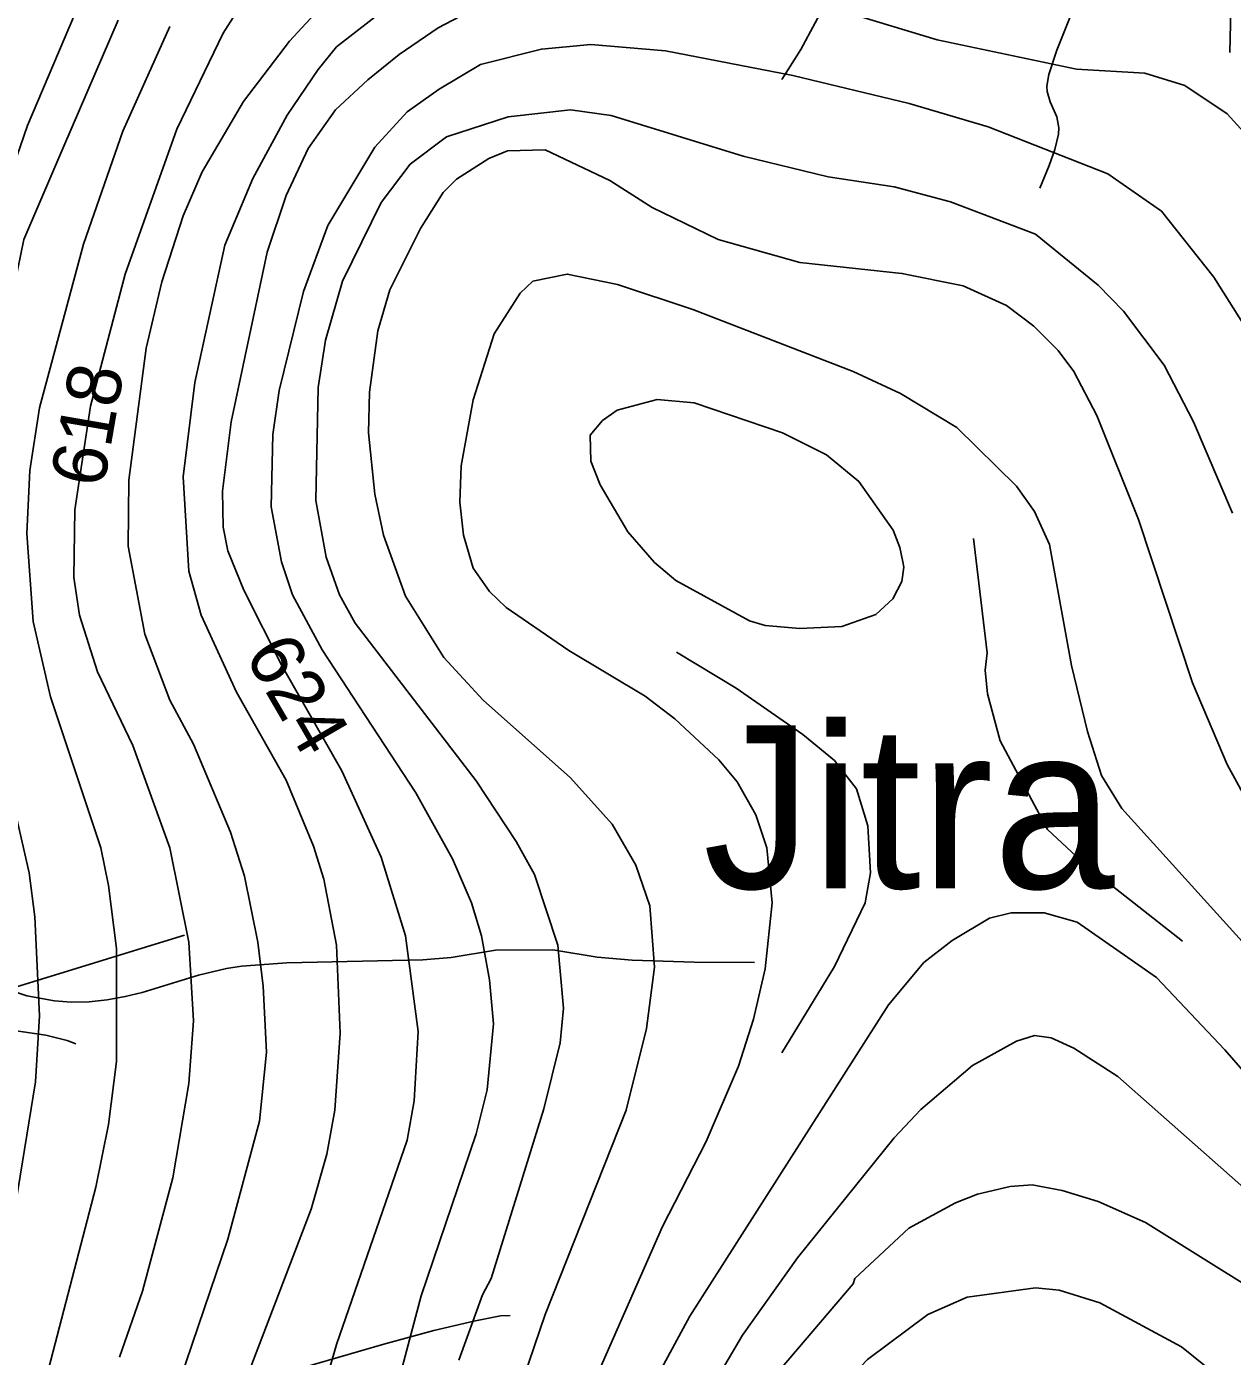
# Model space of a CAD drawing. Extents: x -709584 to -702006, y -1161789 to -1157496.
# Drawn here: x -708273.5 to -708051.5, y -1159639.5 to -1159394.7 of the extents above; entities that cross this region are included whole.
import ezdxf

# ---------------------------------------------------------------- set-up
doc = ezdxf.new("R2010")
doc.units = 0
for name, color, linetype in [('105_místní názvy', 7, 'Continuous'), ('120_vrstevnice hlavní', 7, 'Continuous'), ('121_vrstevnice hlavní_popis', 7, 'Continuous'), ('122_vrstevnice základní', 7, 'Continuous'), ('124_vrstevnice doplňková', 7, 'Continuous'), ('411_akumulovaný odtok', 7, 'Continuous')]:
    doc.layers.add(name, color=color, linetype=linetype)

msp = doc.modelspace()

# ---------------------------------------------------------------- linework, layer by layer
at = {"layer": '120_vrstevnice hlavní'}
for points in [[(-708006.36, -1159424.2), (-708009.48, -1159411.26), (-708013.71, -1159401.03), (-708020.47, -1159391.18), (-708024.76, -1159387.18), (-708031.9, -1159381.61), (-708039.33, -1159378.18), (-708046.76, -1159376.18), (-708054.19, -1159375.75), (-708072.76, -1159376.03), (-708087.62, -1159375.03), (-708105.04, -1159371.89), (-708125.62, -1159365.46), (-708142.76, -1159362.32), (-708156.48, -1159361.46), (-708170.19, -1159361.75), (-708187.33, -1159366.03), (-708197.62, -1159371.75), (-708206.77, -1159378.39), (-708217.52, -1159389.17), (-708225.11, -1159397.44)], [(-708225.12, -1159397.44), (-708233.59, -1159408.55), (-708241.24, -1159421.51), (-708244.71, -1159429.61), (-708248.62, -1159441.76), (-708251.51, -1159453.91), (-708254.69, -1159478.21), (-708254.83, -1159490.36), (-708251.8, -1159506.56), (-708247.17, -1159518.71), (-708242.83, -1159526.81), (-708236.03, -1159543.01), (-708233.43, -1159551.11), (-708230.97, -1159563.26), (-708229.96, -1159571.36), (-708229.38, -1159583.51), (-708230.68, -1159596.24), (-708236.46, -1159617.94), (-708246.3, -1159646.87)], [(-708044.23, -1159545.62), (-708052.48, -1159530.57), (-708058.84, -1159515.53), (-708068.82, -1159485.45), (-708076.49, -1159466.35), (-708080.68, -1159458.25), (-708083.58, -1159454.35), (-708088.06, -1159449.86), (-708093.12, -1159446.1), (-708101.08, -1159442.49), (-708112.36, -1159440.17), (-708131.16, -1159438.15), (-708146.21, -1159433.95), (-708158.36, -1159428.02), (-708166.17, -1159423.1), (-708178.03, -1159417.46), (-708184.97, -1159417.61), (-708188.44, -1159419.05), (-708194.37, -1159422.81), (-708196.83, -1159425.27), (-708201.03, -1159431.93), (-708206.67, -1159443.21), (-708208.84, -1159450.73), (-708210.43, -1159462.01), (-708210.57, -1159469.53), (-708209.42, -1159480.82), (-708207.83, -1159488.34), (-708203.78, -1159499.62), (-708196.69, -1159510.9), (-708189.46, -1159518.71), (-708173.4, -1159533.03), (-708165.73, -1159541.57), (-708161.39, -1159549.09), (-708158.79, -1159556.61), (-708157.92, -1159567.89), (-708159.37, -1159579.18), (-708163.13, -1159594.22), (-708178.03, -1159631.82)], [(-708183.23, -1159919.09), (-708173.43, -1159906.12), (-708162.84, -1159889.73), (-708160.09, -1159880.61), (-708157.2, -1159867.6), (-708155.9, -1159854.58), (-708155.9, -1159841.56), (-708158.36, -1159801.2), (-708156.91, -1159759.69), (-708152.86, -1159729.61), (-708146.93, -1159695.76), (-708139.26, -1159673.19), (-708133.97, -1159661.41), (-708125.81, -1159647.59), (-708118.72, -1159640.07), (-708107.59, -1159631.82), (-708100.35, -1159628.64), (-708087.77, -1159626.91), (-708083.43, -1159627.34), (-708075.91, -1159629.66), (-708060.87, -1159637.76), (-708033.09, -1159660.18)], [(-708178.03, -1159631.82), (-708187, -1159658.15), (-708192.93, -1159684.48), (-708196.98, -1159707.04), (-708201.9, -1159740.89), (-708203.49, -1159759.69), (-708204.35, -1159783.99), (-708202.18, -1159825.65), (-708204.06, -1159841.56), (-708207.39, -1159853.71), (-708214.33, -1159872.8), (-708235.16, -1159914.17), (-708252.09, -1159951.78), (-708262.21, -1159970.58), (-708281.88, -1159998.93), (-708292.44, -1160017.74), (-708313.42, -1160064.02), (-708336.41, -1160105.97)]]:
    msp.add_lwpolyline(points, dxfattribs=at)
msp.add_open_spline([(-708225.11, -1159397.44), (-708225.12, -1159397.44)], degree=1, dxfattribs=at)
at = {"layer": '122_vrstevnice základní'}
for points in [[(-708237.32, -1159395.95), (-708230.54, -1159385.25), (-708221.75, -1159375.45), (-708212.63, -1159367.61), (-708198.19, -1159358.18), (-708191.33, -1159354.89), (-708187.19, -1159353.75), (-708187.05, -1159353.32), (-708175.05, -1159350.6), (-708165.05, -1159349.46), (-708157.05, -1159349.46), (-708145.05, -1159350.6), (-708132.19, -1159353.17), (-708110.76, -1159358.75), (-708081.33, -1159363.18), (-708041.33, -1159363.75), (-708030.18, -1159365.89), (-708023.33, -1159368.75), (-708017.61, -1159373.03), (-708012.33, -1159378.75), (-708004.75, -1159390.46), (-708000.69, -1159398.78), (-707996.45, -1159413.48), (-707994.48, -1159425.66)], [(-708021.96, -1159422.29), (-708025.43, -1159412.46), (-708028.69, -1159406.91), (-708034.55, -1159400.05), (-708038.61, -1159396.61), (-708046.76, -1159392.32), (-708052.19, -1159390.61), (-708062.47, -1159388.61), (-708083.04, -1159387.03), (-708095.04, -1159384.89), (-708129.33, -1159376.89), (-708146.48, -1159374.6), (-708155.05, -1159374.18), (-708165.33, -1159374.6), (-708175.62, -1159376.32), (-708180.76, -1159377.75), (-708189.32, -1159380.9), (-708199.09, -1159386.13), (-708206.9, -1159391.03), (-708216.45, -1159398.5)], [(-708204.96, -1159399.91), (-708197.73, -1159394.95), (-708193.76, -1159392.89), (-708187.91, -1159390.32), (-708181.05, -1159388.61), (-708167.33, -1159387.32), (-708150.76, -1159387.18), (-708141.9, -1159387.89), (-708128.19, -1159390.46), (-708105.9, -1159397.18), (-708080.19, -1159402.61), (-708067.61, -1159403.32), (-708060.28, -1159405.6), (-708052.46, -1159410.83), (-708044.57, -1159419.53)], [(-708264.75, -1159392.59), (-708273.37, -1159412.97), (-708280.58, -1159433.66), (-708292.15, -1159482.26), (-708293.31, -1159491.52), (-708293.45, -1159514.66), (-708289.98, -1159542.44), (-708287.67, -1159556.32), (-708286.8, -1159565.58), (-708286.66, -1159581.78), (-708287.52, -1159595.66), (-708290.27, -1159616.49), (-708298.08, -1159644.27)], [(-708256.7, -1159393.58), (-708266.7, -1159416.77), (-708274.07, -1159433.95), (-708280.73, -1159466.35), (-708283.33, -1159486.31), (-708282.75, -1159505.98), (-708281.02, -1159516.11), (-708273.06, -1159550.53), (-708272.05, -1159558.64), (-708271.18, -1159576.86), (-708271.9, -1159589.01), (-708275.52, -1159611.29), (-708285.64, -1159647.74)], [(-708271.04, -1159647.74), (-708260.77, -1159608.39), (-708258.45, -1159596.82), (-708257, -1159585.25), (-708257, -1159564.42), (-708258.45, -1159552.85), (-708259.9, -1159545.91), (-708269.15, -1159518.14), (-708272.34, -1159504.25), (-708273.49, -1159488.05), (-708272.92, -1159476.48), (-708271.18, -1159464.91), (-708263.08, -1159434.82), (-708255.85, -1159413.99), (-708247.14, -1159394.75)], [(-708237.32, -1159395.95), (-708245.87, -1159413.61), (-708255.41, -1159440.32), (-708261.78, -1159464.62), (-708264.67, -1159483.71), (-708264.82, -1159496.15), (-708263.8, -1159503.09), (-708260.48, -1159513.51), (-708253.97, -1159527.1), (-708247.17, -1159545.91), (-708243.7, -1159563.26), (-708242.83, -1159577.73), (-708243.7, -1159589.3), (-708246.59, -1159606.66), (-708252.23, -1159627.49), (-708256.43, -1159639.64)], [(-708216.45, -1159398.5), (-708219.86, -1159402.62), (-708225.58, -1159411.04), (-708231.87, -1159422.71), (-708237.04, -1159434.96), (-708242.54, -1159460.28), (-708244.71, -1159477.63), (-708243.7, -1159494.99), (-708241.38, -1159503.09), (-708234.87, -1159517.27), (-708225.76, -1159533.47), (-708220.7, -1159545.62), (-708218.82, -1159551.69), (-708216.5, -1159563.84), (-708215.78, -1159580.04), (-708216.79, -1159594.22), (-708218.24, -1159602.32), (-708221.13, -1159612.44), (-708235.89, -1159650.92)], [(-708096.48, -1159413.18), (-708111.05, -1159408.89), (-708132.47, -1159403.75), (-708155.9, -1159399.18), (-708169.62, -1159398.03), (-708178.76, -1159398.89), (-708189.99, -1159401.74)], [(-708221.86, -1159656.12), (-708216.5, -1159637.32), (-708203.49, -1159599.71), (-708202.18, -1159592.48), (-708201.46, -1159579.75), (-708203.78, -1159562.11), (-708208.26, -1159547.64), (-708215.49, -1159531.73), (-708226.48, -1159512.49), (-708233.57, -1159498.46), (-708236.46, -1159491.23), (-708237.33, -1159486.89), (-708237.48, -1159480.24), (-708235.89, -1159467.51), (-708229.23, -1159436.27), (-708225.76, -1159425.85), (-708221.71, -1159417.17), (-708216.65, -1159410.08), (-708210.73, -1159404.53), (-708204.96, -1159399.91)], [(-708208.84, -1159658.44), (-708200.88, -1159628.35), (-708190.76, -1159598.56), (-708188.73, -1159590.46), (-708187.58, -1159578.31), (-708188.3, -1159570.21), (-708189.75, -1159562.11), (-708191.62, -1159556.03), (-708195.1, -1159547.93), (-708201.9, -1159535.78), (-708219.11, -1159509.46), (-708224.6, -1159499.33), (-708226.63, -1159493.26), (-708228.51, -1159483.13), (-708228.22, -1159469.82), (-708227.06, -1159461.72), (-708222.58, -1159443.5), (-708218.09, -1159431.35), (-708209.4, -1159416.97), (-708203.49, -1159410.46), (-708197.58, -1159406.26), (-708189.99, -1159401.74)], [(-708051.46, -1159484.29), (-708058.7, -1159467.51), (-708064.05, -1159457.09), (-708071.57, -1159447.11), (-708076.2, -1159442.34), (-708087.77, -1159432.94), (-708103.39, -1159427.01), (-708113.81, -1159424.26), (-708125.96, -1159422.38), (-708141.58, -1159418.62), (-708165.88, -1159411.1), (-708173.4, -1159410.08), (-708184.88, -1159411.35), (-708196.22, -1159415.02), (-708202.91, -1159420.07), (-708208.26, -1159427.15), (-708215.35, -1159441.62), (-708218.53, -1159452.47), (-708219.83, -1159461.15), (-708220.26, -1159481.97), (-708218.38, -1159492.39), (-708215.93, -1159499.33), (-708213.03, -1159504.54), (-708190.76, -1159533.61), (-708183.38, -1159544.75), (-708180.05, -1159550.82), (-708175.71, -1159563.84), (-708174.7, -1159575.41), (-708175.28, -1159581.78), (-708178.32, -1159593.93), (-708188.01, -1159625.17), (-708189.6, -1159628.21), (-708193.94, -1159640.21)], [(-708048.57, -1159451.02), (-708054.94, -1159440.89), (-708064.55, -1159428.75), (-708074.46, -1159421.86), (-708096.47, -1159413.18)], [(-708170.22, -1159646.87), (-708156.48, -1159615.62), (-708148.38, -1159600), (-708142.45, -1159586.12), (-708139.7, -1159577.44), (-708137.53, -1159568.18), (-708136.23, -1159556.03), (-708137.24, -1159545.91), (-708139.26, -1159539.83), (-708142.73, -1159533.76), (-708146.06, -1159529.71), (-708154.16, -1159522.18), (-708159.66, -1159517.99), (-708173.69, -1159509.6), (-708185.26, -1159501.65), (-708188.3, -1159498.75), (-708191.34, -1159494.41), (-708193.07, -1159488.34), (-708193.8, -1159482.26), (-708193.51, -1159475.61), (-708191.34, -1159463.46), (-708187.43, -1159451.31), (-708182.66, -1159443.79), (-708180.34, -1159441.62), (-708173.98, -1159440.31), (-708164.72, -1159442.2), (-708150.84, -1159446.82), (-708121.33, -1159458.25), (-708112.65, -1159462.3)], [(-708112.65, -1159462.3), (-708102.23, -1159468.52), (-708091.24, -1159479.37), (-708087.92, -1159484), (-708085.17, -1159490.07), (-708081.12, -1159512.35), (-708078.22, -1159524.5), (-708075.62, -1159532.6), (-708071.86, -1159538.67), (-708035.7, -1159578.6)], [(-708164.79, -1159465.38), (-708157.43, -1159463.36), (-708150.63, -1159464), (-708134.35, -1159469.53), (-708126.25, -1159473.58), (-708120.32, -1159478.5), (-708113.95, -1159487.47), (-708112.75, -1159490.66), (-708112.21, -1159493.26), (-708111.98, -1159494.26), (-708112.36, -1159496.87), (-708114.05, -1159500.07), (-708117.15, -1159502.99), (-708123.45, -1159505.19), (-708131.16, -1159505.55), (-708137.53, -1159504.97), (-708140.42, -1159504.1), (-708154.02, -1159496.73), (-708157.92, -1159493.4), (-708162.84, -1159487.76), (-708167.9, -1159479.08), (-708169.64, -1159474.74), (-708169.78, -1159469.97), (-708167.52, -1159467.28), (-708164.79, -1159465.38)], [(-708157.06, -1159642.53), (-708151.41, -1159632.11), (-708114.82, -1159574.83), (-708108.31, -1159567.02), (-708103.1, -1159562.97), (-708096.25, -1159558.84), (-708092.22, -1159557.86), (-708086.17, -1159557.86), (-708080.12, -1159559.57), (-708065.5, -1159569.77), (-708052.91, -1159583.08), (-708033.53, -1159605.36)], [(-708026.73, -1159628.5), (-708072.58, -1159588), (-708080.68, -1159582.79), (-708084.88, -1159580.91), (-708087.92, -1159580.48), (-708091.24, -1159581.49), (-708099.34, -1159585.97), (-708108.89, -1159594.07), (-708113.81, -1159599.28), (-708131.6, -1159621.41), (-708141.72, -1159635.59), (-708146.79, -1159644.27)], [(-708134.78, -1159641.95), (-708121.33, -1159626.18), (-708121.04, -1159625.17), (-708111.06, -1159615.91), (-708102.52, -1159611.28), (-708098.47, -1159609.69), (-708092.4, -1159608.25), (-708088.35, -1159607.96), (-708082.85, -1159608.97), (-708076.2, -1159611), (-708067.52, -1159614.9), (-708047.27, -1159627.49)]]:
    msp.add_lwpolyline(points, dxfattribs=at)
for points in [[(-708247.14, -1159394.75), (-708247.14, -1159394.75)], [(-708237.32, -1159395.95), (-708237.32, -1159395.95)], [(-708216.45, -1159398.5), (-708216.45, -1159398.5)], [(-708204.96, -1159399.91), (-708204.96, -1159399.91)], [(-708189.99, -1159401.74), (-708189.99, -1159401.74)], [(-708096.47, -1159413.18), (-708096.48, -1159413.18)]]:
    msp.add_open_spline(points, degree=1, dxfattribs=at)
at = {"layer": '124_vrstevnice doplňková'}
for points in [[(-708099.19, -1159488.99), (-708096.67, -1159510.03), (-708097.03, -1159513.22), (-708096.59, -1159517.56), (-708094.28, -1159526.24), (-708085.56, -1159542.53), (-708078.51, -1159549.09), (-708060.72, -1159563.12)], [(-708153.86, -1159509.87), (-708142.88, -1159516.54), (-708130.58, -1159525.08), (-708124.8, -1159529.85), (-708120.75, -1159535.06), (-708118.61, -1159541.84), (-708118.15, -1159550.53), (-708119.16, -1159556.03), (-708124.8, -1159567.75), (-708134.49, -1159583.66)]]:
    msp.add_lwpolyline(points, dxfattribs=at)
at = {"layer": '411_akumulovaný odtok'}
msp.add_line((-708244.49, -1159562), (-708276.99, -1159572), dxfattribs=at)
for points in [[(-708051.99, -1159399.5), (-708051.72, -1159388.99), (-708050.37, -1159359.14)], [(-708086.99, -1159424.5), (-708085.25, -1159420.32), (-708084.23, -1159417.4), (-708083.55, -1159414.57), (-708083.45, -1159413.36), (-708083.82, -1159411.38), (-708085.04, -1159408.62), (-708085.61, -1159406.72), (-708085.65, -1159405.69), (-708085.33, -1159403.54), (-708083.85, -1159399.07), (-708078.86, -1159386.56), (-708078.17, -1159384.28), (-708077.81, -1159381.99), (-708077.94, -1159379.7), (-708078.48, -1159377.21), (-708081.99, -1159367)], [(-708134.49, -1159404.5), (-708130.96, -1159398.96), (-708125.67, -1159389.09)], [(-708264.49, -1159582), (-708266.1, -1159581.39), (-708269.99, -1159580.42), (-708279.68, -1159578.97), (-708282.58, -1159578.25), (-708290.19, -1159575.63), (-708292.4, -1159575.07), (-708294.66, -1159574.79), (-708301.65, -1159574.4), (-708307.72, -1159573.3), (-708313.09, -1159572.64), (-708330.12, -1159571.75), (-708335.76, -1159571.22), (-708338.52, -1159570.79), (-708341.22, -1159570.19), (-708347.59, -1159568.16), (-708353.24, -1159566.58), (-708362.01, -1159564.66), (-708376.95, -1159561.98), (-708406.99, -1159557)], [(-708139.49, -1159567), (-708150.62, -1159566.96), (-708162.04, -1159566.6), (-708168.46, -1159566.06), (-708176.62, -1159564.72), (-708187.21, -1159564.78), (-708195.37, -1159566.09), (-708200.59, -1159566.53), (-708225.64, -1159567.1), (-708233.99, -1159567.72), (-708236.73, -1159568.14), (-708241.89, -1159569.36), (-708252.29, -1159572.56), (-708255.39, -1159573.3), (-708258.68, -1159573.88), (-708262.04, -1159574.24), (-708265.34, -1159574.32), (-708268.4, -1159574.1), (-708273.53, -1159573.16), (-708276.99, -1159572)], [(-708184.49, -1159632), (-708186.31, -1159632.08), (-708191.18, -1159633.05), (-708198.53, -1159634.79), (-708207.75, -1159637.25), (-708233.17, -1159644.62)]]:
    msp.add_lwpolyline(points, dxfattribs=at)

# ---------------------------------------------------------------- texts
at = {"layer": '105_místní názvy'}
msp.add_text('Jitra', height=30, dxfattribs=at).set_placement((-708149, -1159553.38))
at = {"layer": '121_vrstevnice hlavní_popis'}
for s, rotation, p in [('618', 80.1811, (-708259.38, -1159479.86)), ('624', 300.1829, (-708233.54, -1159510.42))]:
    msp.add_text(s, height=10, rotation=rotation, dxfattribs=at).set_placement(p)

doc.saveas('drawing.dxf')
